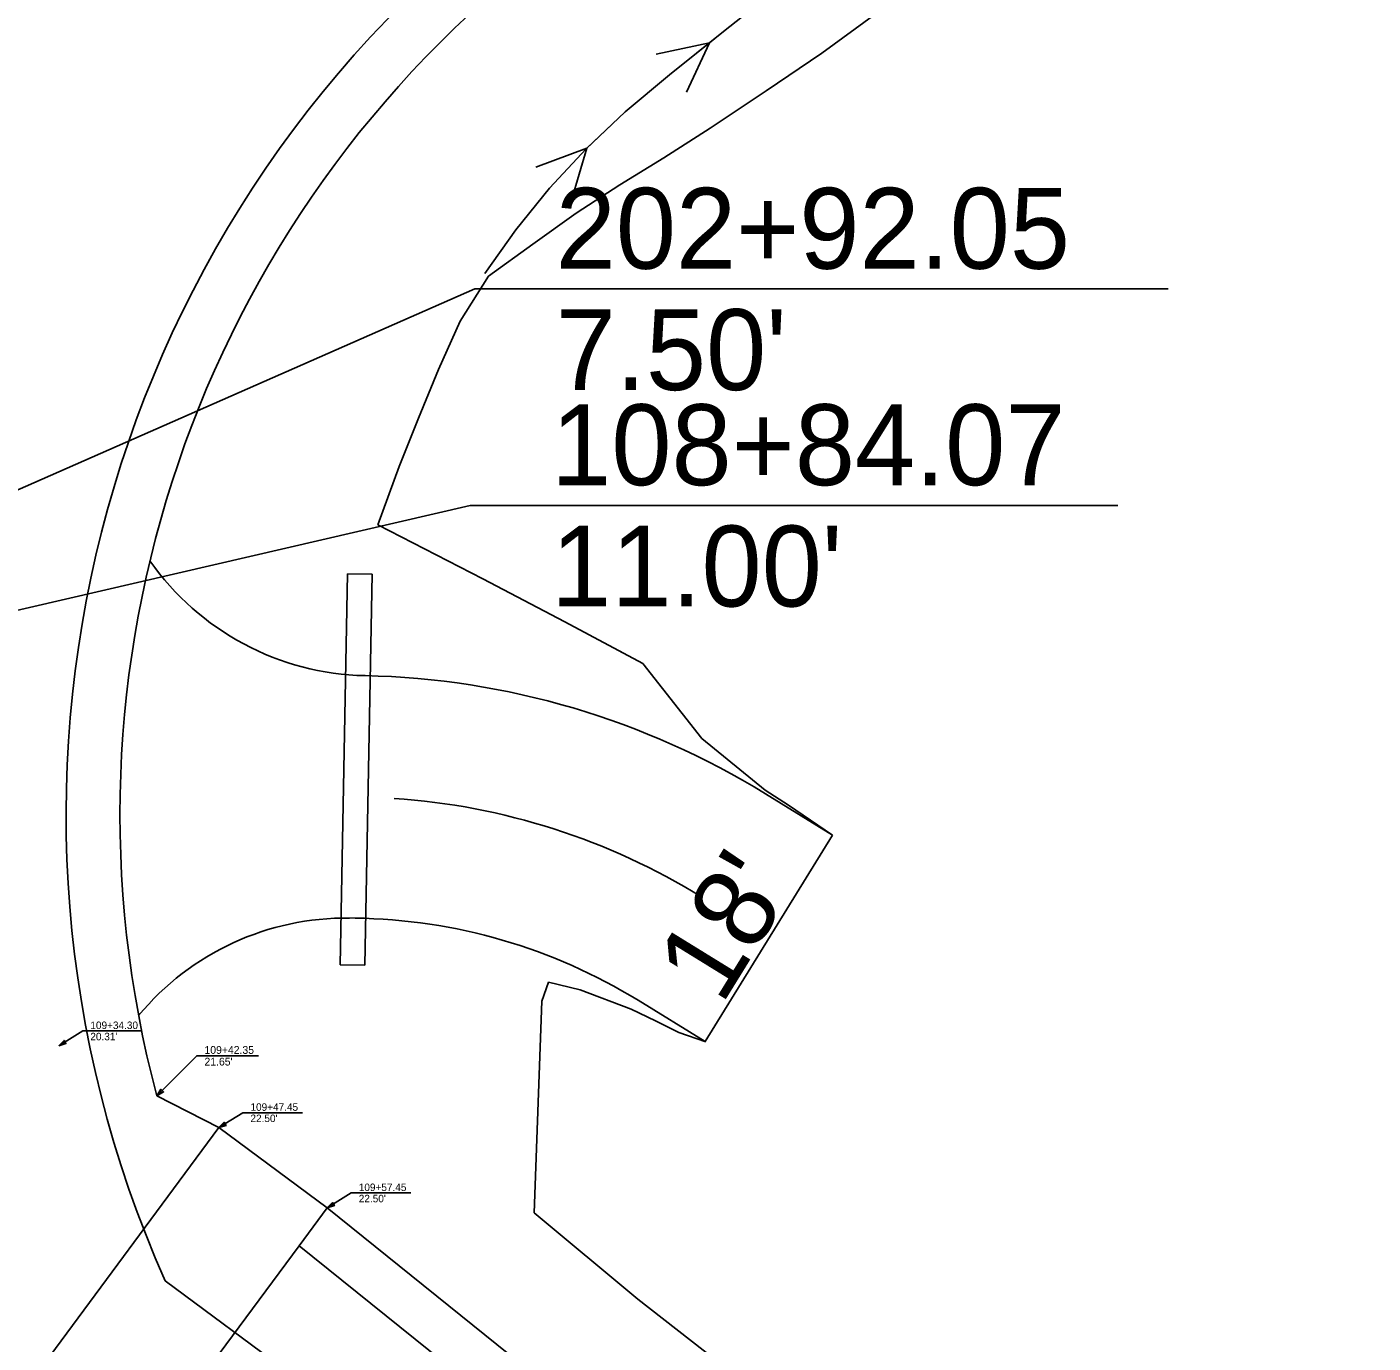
# Model space of a CAD drawing. Extents: x 1006695 to 1009377, y 1883329 to 1886115.
# Drawn here: x 1007700.6 to 1007800.5, y 1884873.3 to 1884970.9 of the extents above; entities that cross this region are included whole.
import ezdxf

# ---------------------------------------------------------------- set-up
doc = ezdxf.new("R2010")
doc.units = 0
for name, color, linetype in [('R_Drainage Concrete Lining', 7, 'Continuous'), ('R_Drive', 7, 'Continuous'), ('R_No Plot', 7, 'Continuous'), ('R_Prop Const Limits Cut', 7, 'Continuous'), ('R_Prop EOL', 7, 'Continuous'), ('R_Prop EOS', 7, 'Continuous'), ('R_Prop Guardrail', 7, 'Continuous')]:
    doc.layers.add(name, color=color, linetype=linetype)

msp = doc.modelspace()

# ---------------------------------------------------------------- linework, layer by layer
at = {"layer": 'R_Drainage Concrete Lining'}
for p, q in [((1007724.369, 1884930.358), (1007723.836, 1884901.363)), ((1007724.369, 1884930.358), (1007726.202, 1884930.324)), ((1007726.202, 1884930.324), (1007725.669, 1884901.329)), ((1007725.669, 1884901.329), (1007723.836, 1884901.363))]:
    msp.add_line(p, q, dxfattribs=at)
at = {"layer": 'R_Drive'}
for p, q in [((1007755.381, 1884914.044), (1007760.348, 1884910.982)), ((1007760.348, 1884910.982), (1007750.902, 1884895.659)), ((1007723.865, 1884904.831), (1007724.956, 1884904.817)), ((1007745.935, 1884898.722), (1007750.902, 1884895.659))]:
    msp.add_line(p, q, dxfattribs=at)
for centre, radius, start, end in [((1007726.103, 1884942.802), 20, 215.02752, 268.77901), ((1007724.42, 1884863.82), 59, 58.34807, 88.77901), ((1007724.42, 1884863.82), 50, 58.34807, 86.087), ((1007724.276, 1884884.824), 20, 89.25114, 140.31495), ((1007724.42, 1884863.82), 41, 58.34807, 89.25114)]:
    msp.add_arc(centre, radius, start, end, dxfattribs=at)
at = {"layer": 'R_No Plot'}
for p, q in [((1007739.824, 1884951.494), (1007785.26, 1884951.494)), ((1007739.489, 1884935.437), (1007781.525, 1884935.437)), ((1007705.303, 1884896.45), (1007709.154, 1884896.45)), ((1007713.769, 1884894.604), (1007717.771, 1884894.604)), ((1007717.179, 1884890.382), (1007721.03, 1884890.382)), ((1007714.839, 1884889.272), (1007701.446, 1884871.192)), ((1007725.215, 1884884.43), (1007729.065, 1884884.43))]:
    msp.add_line(p, q, dxfattribs=at)
for points in [[(1007657.067, 1884917.753), (1007733.824, 1884951.494), (1007739.824, 1884951.494)], [(1007657.067, 1884917.753), (1007733.489, 1884935.437), (1007739.489, 1884935.437)], [(1007702.963, 1884895.34), (1007704.747, 1884896.45), (1007705.303, 1884896.45)], [(1007710.237, 1884891.623), (1007713.191, 1884894.604), (1007713.769, 1884894.604)], [(1007714.839, 1884889.272), (1007716.623, 1884890.382), (1007717.179, 1884890.382)], [(1007722.874, 1884883.32), (1007724.659, 1884884.43), (1007725.215, 1884884.43)], [(1007709.482, 1884865.24), (1007720.791, 1884880.507), (1007722.874, 1884883.32)]]:
    msp.add_lwpolyline(points, dxfattribs=at)
for points in [[(1007702.963, 1884895.34), (1007703.35, 1884895.739), (1007703.492, 1884895.511)], [(1007710.237, 1884891.623), (1007710.532, 1884892.12), (1007710.731, 1884891.923)], [(1007714.839, 1884889.272), (1007715.225, 1884889.671), (1007715.368, 1884889.442)], [(1007722.874, 1884883.32), (1007723.261, 1884883.719), (1007723.404, 1884883.49)]]:
    msp.add_lwpolyline(points, close=True, dxfattribs=at)
at = {"layer": 'R_Prop Const Limits Cut'}
for p, q in [((1007751.22, 1884969.757), (1007747.285, 1884968.91)), ((1007751.22, 1884969.757), (1007749.536, 1884966.101)), ((1007742.126, 1884961.939), (1007738.359, 1884960.52)), ((1007742.126, 1884961.939), (1007741, 1884958.074))]:
    msp.add_line(p, q, dxfattribs=at)
for points in [[(1007734.554, 1884952.65), (1007736.859, 1884955.878), (1007739.369, 1884958.962), (1007742.077, 1884961.887), (1007744.972, 1884964.639), (1007748.259, 1884967.385), (1007752.15, 1884970.503), (1007756.049, 1884973.612), (1007759.955, 1884976.712), (1007763.868, 1884979.802), (1007767.788, 1884982.884), (1007771.866, 1884985.757), (1007775.951, 1884988.621), (1007780.042, 1884991.475), (1007784.141, 1884994.319), (1007788.244, 1884997.157), (1007792.35, 1884999.991), (1007792.467, 1885000.072), (1007792.476, 1885000.078), (1007792.481, 1885000.081)], [(1007734.826, 1884952.448), (1007738.136, 1884954.805), (1007741.332, 1884957.105), (1007744.59, 1884959.213), (1007747.834, 1884961.21), (1007751.29, 1884963.426), (1007755.437, 1884966.203), (1007759.573, 1884968.992), (1007763.595, 1884971.931), (1007767.472, 1884975.06), (1007771.298, 1884978.257), (1007775.097, 1884981.491), (1007778.891, 1884984.731), (1007782.706, 1884987.945), (1007786.539, 1884991.136), (1007790.342, 1884994.367), (1007794.728, 1884996.823), (1007794.857, 1884996.887), (1007794.866, 1884996.892), (1007794.872, 1884996.895)], [(1007734.554, 1884952.65), (1007736.859, 1884955.878), (1007739.369, 1884958.962), (1007742.077, 1884961.887), (1007742.129, 1884961.936), (1007744.972, 1884964.639), (1007748.259, 1884967.385), (1007751.22, 1884969.757), (1007752.15, 1884970.503), (1007756.049, 1884973.612)], [(1007726.631, 1884933.987), (1007728.204, 1884938.312), (1007729.634, 1884941.908), (1007731.123, 1884945.516), (1007732.743, 1884949.108), (1007734.826, 1884952.448)], [(1007726.631, 1884933.987), (1007734.416, 1884929.993), (1007740.498, 1884926.805), (1007746.276, 1884923.71), (1007750.657, 1884918.146), (1007755.365, 1884914.301), (1007757.092, 1884913.19)], [(1007743.415, 1884925.243), (1007746.276, 1884923.71), (1007750.657, 1884918.146), (1007755.365, 1884914.301), (1007757.092, 1884913.19), (1007757.102, 1884913.187), (1007760.348, 1884910.982)], [(1007757.092, 1884913.19), (1007757.102, 1884913.187)], [(1007739.284, 1884900.077), (1007738.783, 1884898.65), (1007738.228, 1884882.963), (1007745.919, 1884876.545)], [(1007750.949, 1884895.631), (1007748.95, 1884896.321), (1007747.238, 1884897.185), (1007747.228, 1884897.19), (1007745.409, 1884898.06), (1007741.649, 1884899.493), (1007739.284, 1884900.077)], [(1007745.919, 1884876.545), (1007753.799, 1884870.384), (1007762.039, 1884864.707), (1007770.079, 1884858.761), (1007772.079, 1884857.31), (1007775.19, 1884854.971), (1007778.221, 1884852.678), (1007786.343, 1884846.483), (1007794.612, 1884840.478), (1007800.457, 1884835.431)]]:
    msp.add_lwpolyline(points, dxfattribs=at)
at = {"layer": 'R_Prop EOL'}
msp.add_line((1007710.853, 1884877.913), (1007760.213, 1884841.351), dxfattribs=at)
for centre, radius, start, end in [((1007643.128, 1885116.034), 150, 232.3673, 307.36872), ((1007788.505, 1884912.485), 85, 127.45008, 203.99904)]:
    msp.add_arc(centre, radius, start, end, dxfattribs=at)
at = {"layer": 'R_Prop EOS'}
for p, q in [((1007714.839, 1884889.272), (1007722.874, 1884883.32)), ((1007722.874, 1884883.32), (1007761.863, 1884851.953))]:
    msp.add_line(p, q, dxfattribs=at)
msp.add_lwpolyline([(1007710.237, 1884891.623), (1007714.839, 1884889.272)], dxfattribs=at)
msp.add_arc((1007788.505, 1884912.485), 81, 127.45008, 194.9246, dxfattribs=at)
at = {"layer": 'R_Prop Guardrail'}
msp.add_line((1007759.779, 1884849.139), (1007720.791, 1884880.507), dxfattribs=at)

# ---------------------------------------------------------------- texts
at = {"layer": 'R_Drive'}
msp.add_text("18'", height=6, rotation=58.34807, dxfattribs=at).set_placement((1007752.124, 1884898.283))
at = {"layer": 'R_No Plot'}
for s, p in [('202+92.05', (1007739.824, 1884952.994)), ("7.50'", (1007739.824, 1884943.994)), ('108+84.07', (1007739.489, 1884936.937)), ("11.00'", (1007739.489, 1884927.937))]:
    msp.add_text(s, height=6, rotation=360, dxfattribs=at).set_placement(p)
for s, height, p in [('109+34.30', 0.5559, (1007705.303, 1884896.589)), ("20.31'", 0.5559, (1007705.303, 1884895.755)), ("21.65'", 0.5778, (1007713.769, 1884893.881)), ('109+42.35', 0.5778, (1007713.769, 1884894.748)), ('109+47.45', 0.5559, (1007717.179, 1884890.521)), ("22.50'", 0.5559, (1007717.179, 1884889.687)), ('109+57.45', 0.5559, (1007725.215, 1884884.569)), ("22.50'", 0.5559, (1007725.215, 1884883.735))]:
    msp.add_text(s, height=height, dxfattribs=at).set_placement(p)

doc.saveas('drawing.dxf')
